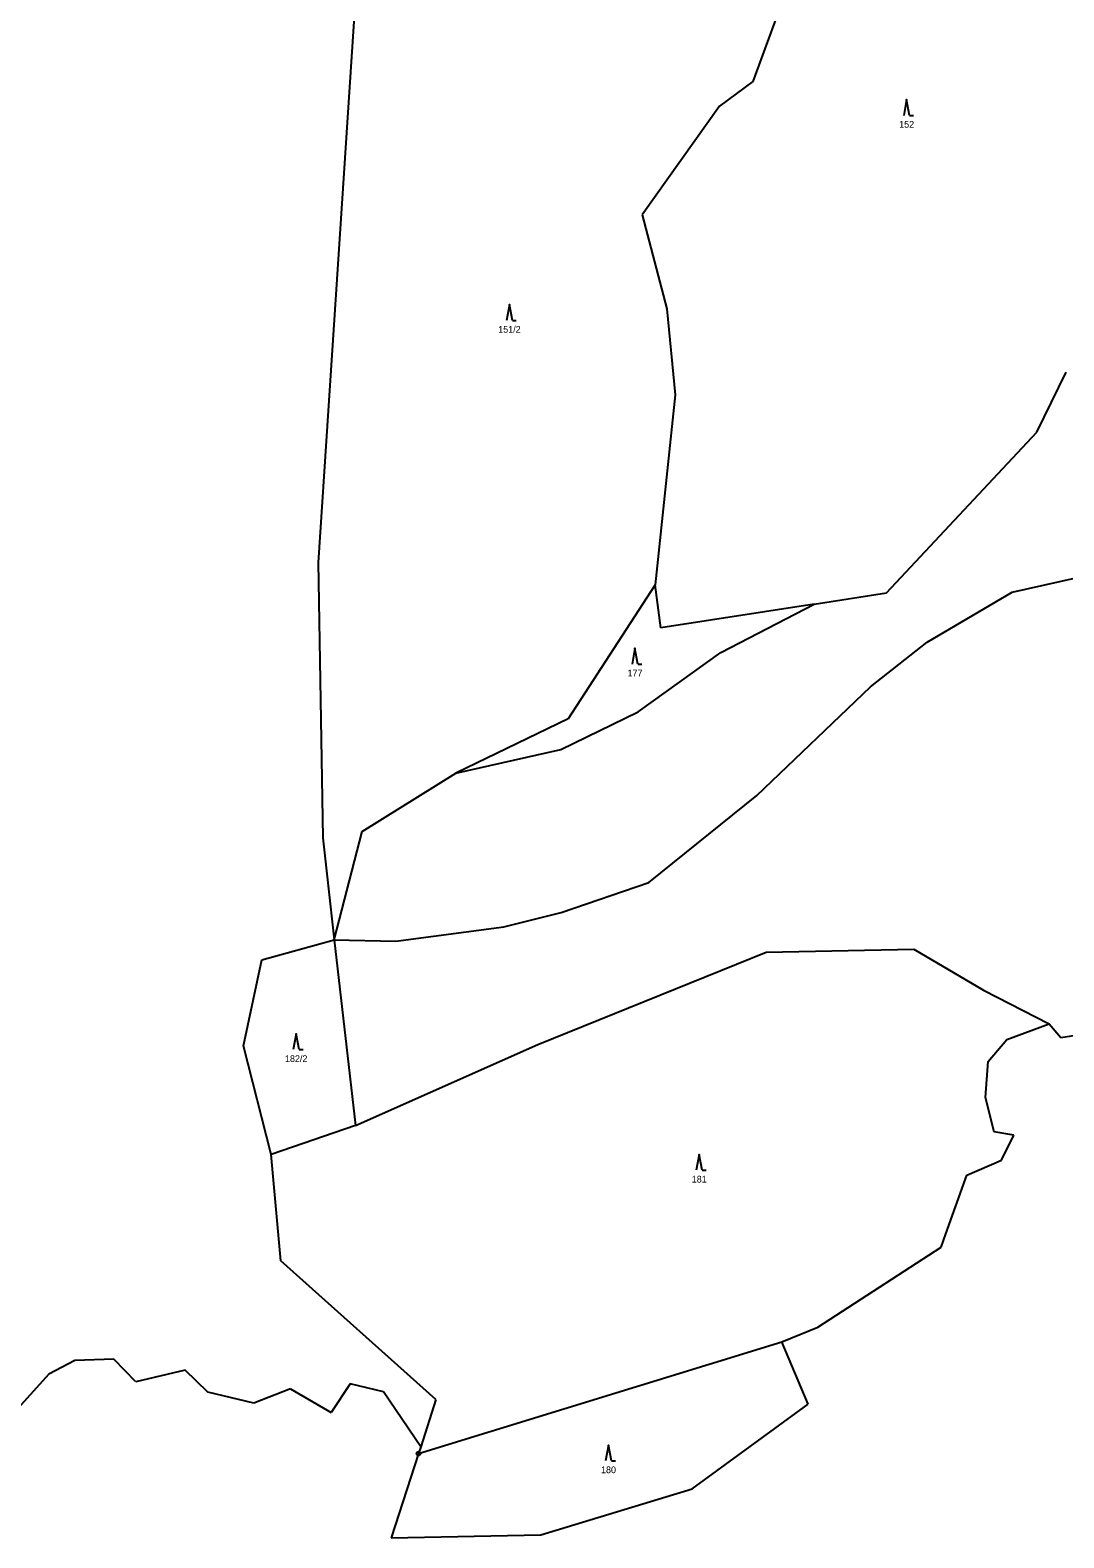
# Model space of a CAD drawing. Extents: x -601877 to -599786, y -1122905 to -1121218.
# Drawn here: x -600889.5 to -600627.6, y -1122825.1 to -1122443.1 of the extents above; entities that cross this region are included whole.
import ezdxf
from ezdxf.enums import TextEntityAlignment as Align

# ---------------------------------------------------------------- set-up
doc = ezdxf.new("R2010")
doc.units = 0
doc.header["$LTSCALE"] = 0.68
for name, color, linetype, lineweight in [('1', 7, 'Continuous', 25), ('3', 7, 'Continuous', 25), ('8', 7, 'Continuous', 25)]:
    doc.layers.add(name, color=color, linetype=linetype, lineweight=lineweight)
doc.layers.add('2', color=7, linetype='Continuous')

msp = doc.modelspace()

# ---------------------------------------------------------------- linework, layer by layer
at = {"layer": '1'}
for p, q in [((-600804.79, -1122399.02), (-600816.51, -1122577.99)), ((-600698.25, -1122433.78), (-600706.41, -1122456.14)), ((-600706.41, -1122456.14), (-600714.84, -1122462.38)), ((-600714.84, -1122462.38), (-600734.43, -1122489.89)), ((-600734.43, -1122489.89), (-600728.18, -1122513.67)), ((-600728.18, -1122513.67), (-600726.08, -1122535.52)), ((-600634.46, -1122544.94), (-600626.99, -1122529.72)), ((-600726.08, -1122535.52), (-600731.12, -1122583.6)), ((-600672.57, -1122585.67), (-600634.46, -1122544.94)), ((-600640.71, -1122585.49), (-600620.03, -1122580.87)), ((-600731.12, -1122583.6), (-600753.23, -1122617.56)), ((-600729.74, -1122594.55), (-600731.12, -1122583.6)), ((-600690.82, -1122588.51), (-600672.57, -1122585.67)), ((-600662.26, -1122598.15), (-600640.71, -1122585.49)), ((-600690.82, -1122588.51), (-600729.74, -1122594.55)), ((-600714.54, -1122600.75), (-600690.82, -1122588.51)), ((-600676.56, -1122609.48), (-600662.26, -1122598.15)), ((-600735.44, -1122615.83), (-600714.54, -1122600.75)), ((-600705.38, -1122637), (-600676.56, -1122609.48)), ((-600753.23, -1122617.56), (-600781.62, -1122631.33)), ((-600755.06, -1122625.36), (-600735.44, -1122615.83)), ((-600781.62, -1122631.33), (-600755.06, -1122625.36)), ((-600805.36, -1122646.14), (-600781.62, -1122631.33)), ((-600732.77, -1122659.01), (-600705.38, -1122637)), ((-600812.51, -1122673.56), (-600805.36, -1122646.14)), ((-600754.98, -1122666.61), (-600732.77, -1122659.01)), ((-600769.5, -1122670.24), (-600754.98, -1122666.61)), ((-600796.89, -1122673.87), (-600769.5, -1122670.24)), ((-600830.8, -1122678.63), (-600812.51, -1122673.56)), ((-600812.51, -1122673.56), (-600796.89, -1122673.87)), ((-600812.51, -1122673.56), (-600807.04, -1122720.61)), ((-600835.45, -1122700.39), (-600830.8, -1122678.63)), ((-600760.88, -1122700.1), (-600703.05, -1122676.69)), ((-600703.05, -1122676.69), (-600665.62, -1122675.97)), ((-600665.62, -1122675.97), (-600647.99, -1122686.34)), ((-600647.99, -1122686.34), (-600631.35, -1122694.86)), ((-600642.05, -1122698.78), (-600631.35, -1122694.86)), ((-600631.35, -1122694.86), (-600628.34, -1122698.31)), ((-600628.34, -1122698.31), (-600621.34, -1122697.21)), ((-600828.4, -1122727.92), (-600835.45, -1122700.39)), ((-600807.04, -1122720.61), (-600760.88, -1122700.1)), ((-600646.74, -1122704.4), (-600642.05, -1122698.78)), ((-600647.44, -1122713.54), (-600646.74, -1122704.4)), ((-600645.28, -1122722.23), (-600647.44, -1122713.54)), ((-600807.04, -1122720.61), (-600828.4, -1122727.92)), ((-600640.31, -1122723.06), (-600645.28, -1122722.23)), ((-600643.4, -1122729.4), (-600640.31, -1122723.06)), ((-600825.96, -1122754.93), (-600828.4, -1122727.92)), ((-600652.17, -1122733.19), (-600643.4, -1122729.4)), ((-600657.46, -1122748.03), (-600652.17, -1122733.19)), ((-600689.94, -1122771.69), (-600658.68, -1122751.46)), ((-600658.68, -1122751.46), (-600657.46, -1122748.03)), ((-600786.72, -1122789.99), (-600825.96, -1122754.93)), ((-600699.08, -1122775.42), (-600689.94, -1122771.69)), ((-600791.11, -1122803.71), (-600699.08, -1122775.42)), ((-600692.34, -1122791.2), (-600699.08, -1122775.42)), ((-600878.18, -1122780.11), (-600884.74, -1122783.58)), ((-600868.28, -1122779.78), (-600878.18, -1122780.11)), ((-600862.77, -1122785.54), (-600868.28, -1122779.78)), ((-600884.74, -1122783.58), (-600894.27, -1122794.05)), ((-600850.2, -1122782.57), (-600862.77, -1122785.54)), ((-600844.47, -1122788.19), (-600850.2, -1122782.57)), ((-600832.84, -1122790.97), (-600844.47, -1122788.19)), ((-600823.57, -1122787.32), (-600832.84, -1122790.97)), ((-600823.57, -1122787.32), (-600813.22, -1122793.33)), ((-600808.46, -1122786.05), (-600813.22, -1122793.33)), ((-600800.01, -1122788.1), (-600808.46, -1122786.05)), ((-600790.56, -1122802.02), (-600800.01, -1122788.1)), ((-600786.72, -1122789.99), (-600790.56, -1122802.02)), ((-600721.73, -1122812.67), (-600692.34, -1122791.2)), ((-600791.11, -1122803.71), (-600798.06, -1122825.07)), ((-600790.56, -1122802.02), (-600791.11, -1122803.71)), ((-600760.1, -1122824.31), (-600721.73, -1122812.67)), ((-600798.06, -1122825.07), (-600760.1, -1122824.31))]:
    msp.add_line(p, q, dxfattribs=at)
msp.add_lwpolyline([(-600816.51, -1122577.99), (-600815.34, -1122647.73), (-600812.51, -1122673.56)], dxfattribs=at)
at = {"layer": '3'}
for p, q in [((-600666.68, -1122464.69), (-600665.684, -1122464.69)), ((-600767.32, -1122516.64), (-600766.324, -1122516.64)), ((-600735.51, -1122603.7), (-600734.514, -1122603.7)), ((-600821.35, -1122701.39), (-600820.354, -1122701.39)), ((-600719.23, -1122731.93), (-600718.234, -1122731.93)), ((-600742.22, -1122805.56), (-600741.224, -1122805.56))]:
    msp.add_line(p, q, dxfattribs=at)
for points in [[(-600666.68, -1122464.69), (-600667.43, -1122460.69), (-600668.18, -1122464.69)], [(-600767.32, -1122516.64), (-600768.07, -1122512.64), (-600768.82, -1122516.64)], [(-600735.51, -1122603.7), (-600736.26, -1122599.7), (-600737.01, -1122603.7)], [(-600821.35, -1122701.39), (-600822.1, -1122697.39), (-600822.85, -1122701.39)], [(-600719.23, -1122731.93), (-600719.98, -1122727.93), (-600720.73, -1122731.93)], [(-600742.22, -1122805.56), (-600742.97, -1122801.56), (-600743.72, -1122805.56)]]:
    msp.add_lwpolyline(points, dxfattribs=at)
at = {"layer": '8'}
for radius in [0.5, 0.0303]:
    msp.add_circle((-600791.11, -1122803.7099), radius, dxfattribs=at)

# ---------------------------------------------------------------- texts
at = {"layer": '2'}
for s, p in [('152', (-600667.429, -1122467.815)), ('151/2', (-600768.07, -1122519.765)), ('177', (-600736.259, -1122606.825)), ('182/2', (-600822.1, -1122704.515)), ('181', (-600719.979, -1122735.055)), ('180', (-600742.969, -1122808.685))]:
    msp.add_text(s, height=1.7, dxfattribs=at).set_placement(p, align=Align.CENTER)

doc.saveas('drawing.dxf')
